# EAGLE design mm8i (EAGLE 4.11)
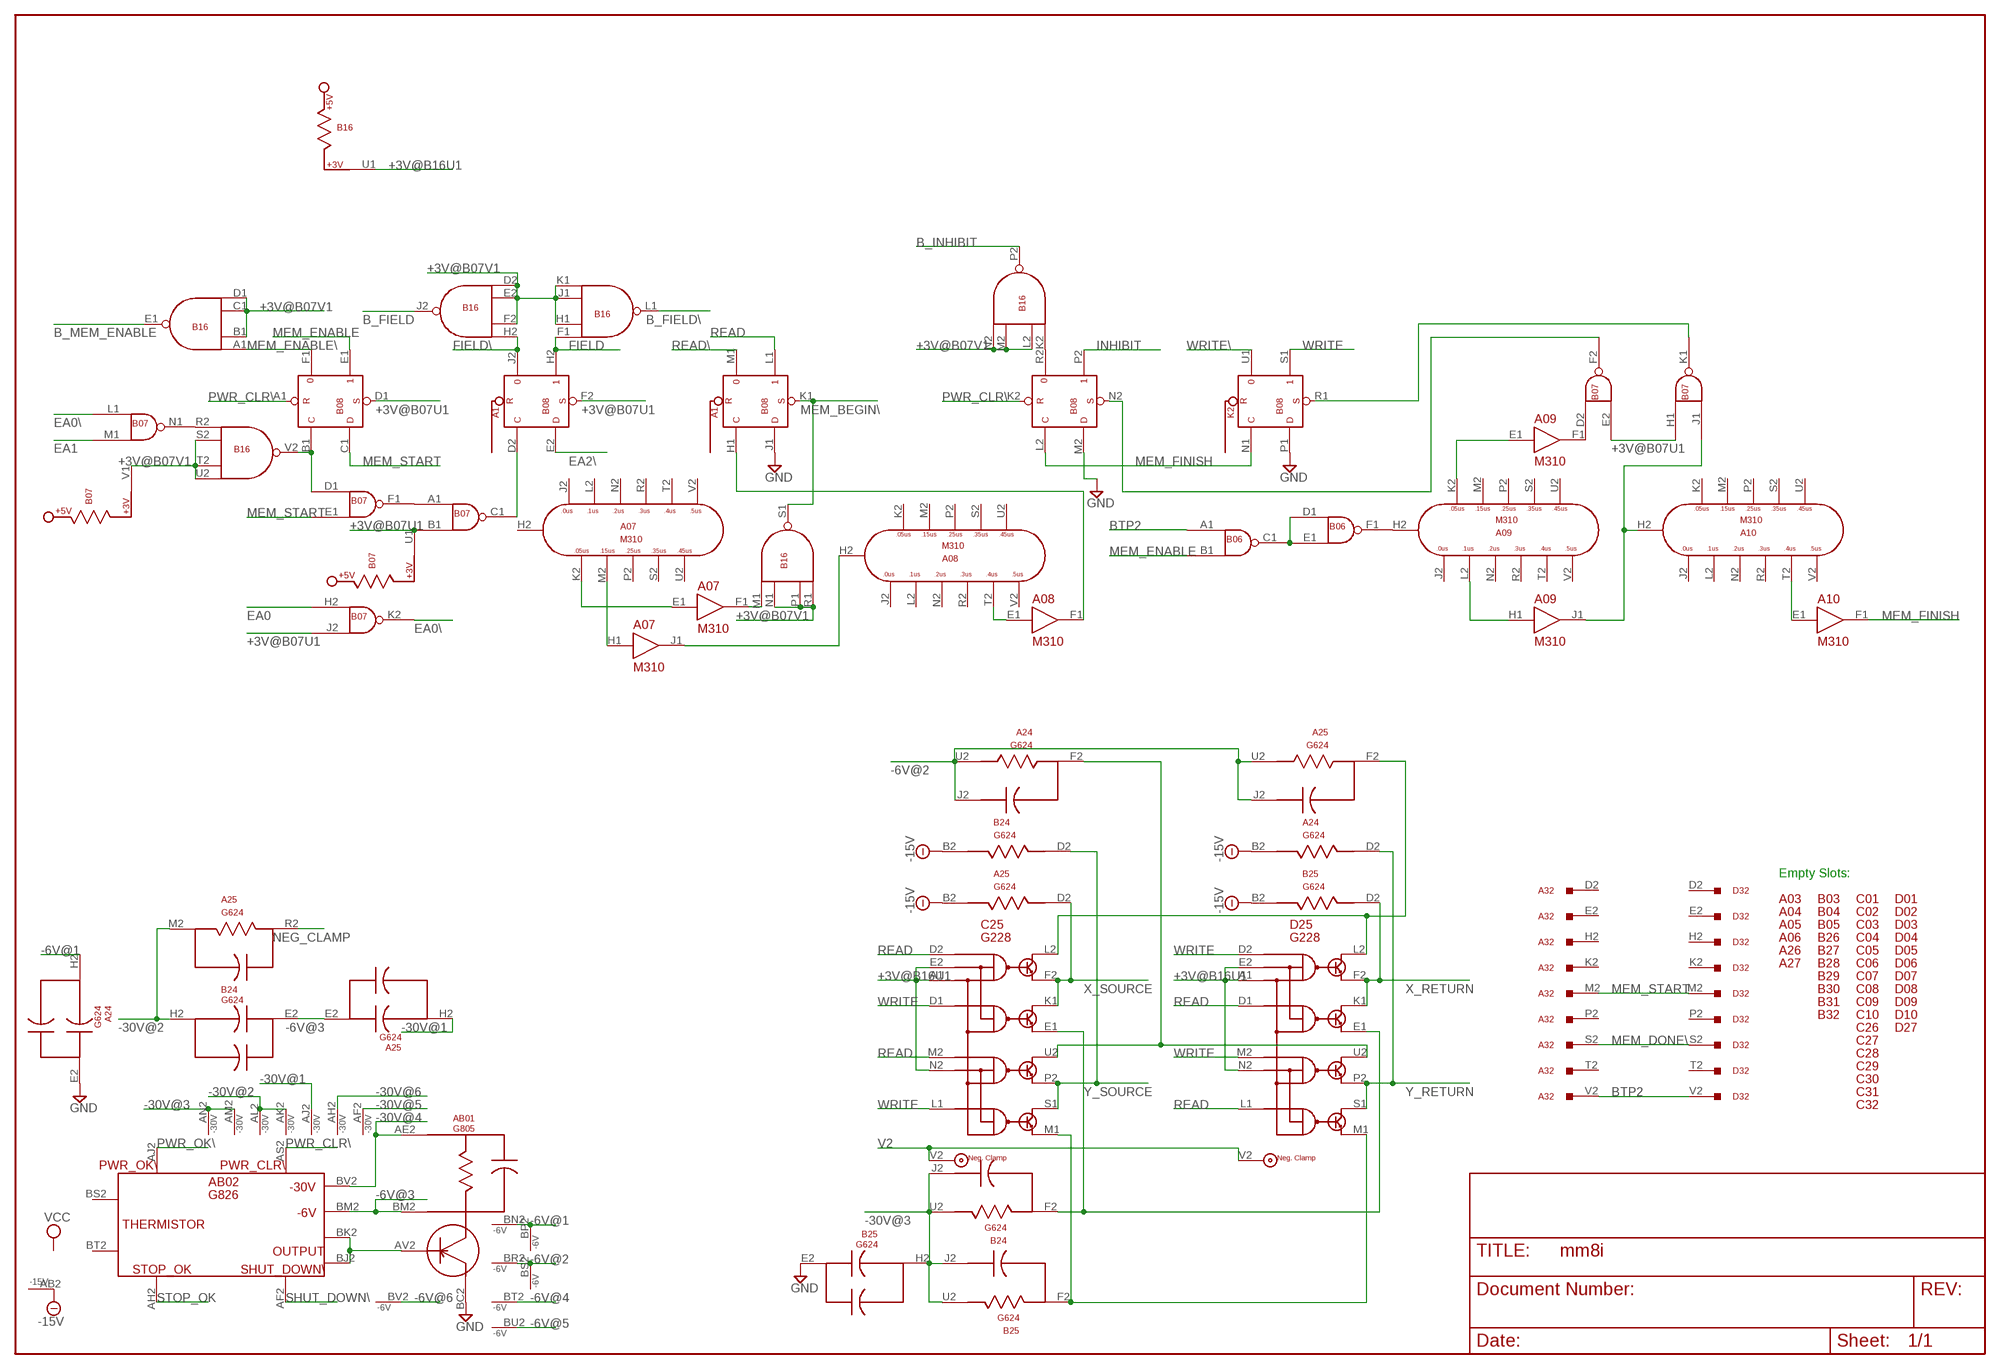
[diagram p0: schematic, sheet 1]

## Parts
A03  H807  [H807]
A04  H807  [H807]
A05  H807  [H807]
A06  H807  [H807]
A07  M310  [H807]
A08  M310  [H807]
A09  M310  [H807]
A10  M310  [H807]
A24  G624  [H807]
A25  G624  [H807]
A26  H807  [H807]
A27  H807  [H807]
A32  W033  W011  [H807]
AB01  G805  [H807-2]
AB02  G826  [H807-2]
B03  H807  [H807]
B04  H807  [H807]
B05  H807  [H807]
B06  M113  [H807]
B07  M113  [H807]
B08  M216  M206X  [H807]
B16  M617  [H807]
B24  G624  [H807]
B25  G624  [H807]
B26  H807  [H807]
B27  H807  [H807]
B28  H807  [H807]
B29  H807  [H807]
B30  H807  [H807]
B31  H807  [H807]
B32  H807  [H807]
C01  H807  [H807]
C02  H807  [H807]
C03  H807  [H807]
C04  H807  [H807]
C05  H807  [H807]
C06  H807  [H807]
C07  H807  [H807]
C08  H807  [H807]
C09  H807  [H807]
C10  H807  [H807]
C25  G228  [H807]
C26  H807  [H807]
C27  H807  [H807]
C28  H807  [H807]
C29  H807  [H807]
C30  H807  [H807]
C31  H807  [H807]
C32  H807  [H807]
D01  H807  [H807]
D02  H807  [H807]
D03  H807  [H807]
D04  H807  [H807]
D05  H807  [H807]
D06  H807  [H807]
D07  H807  [H807]
D08  H807  [H807]
D09  H807  [H807]
D10  H807  [H807]
D25  G228  [H807]
D27  H807  [H807]
D32  W033  W011  [H807]

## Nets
+3V@B07U1: B07.B1(IN2) B07.E2(IN2) B07.H1(IN1) B07.J2(IN2) B07.U1 B08.D1(A1:S) B08.F2(A1B:S)
+3V@B07V1: B07.V1 B16.B1(IN2) B16.C1(IN3) B16.D1(IN4) B16.D2(IN1) B16.E2(IN2) B16.F2(IN3) B16.H1(IN2) B16.J1(IN3) B16.K1(IN4) B16.L2(IN2) B16.M2(IN3) B16.N1(IN2) B16.N2(IN4) B16.P1(IN3) B16.R1(IN4) B16.S2(IN2) B16.T2(IN3) B16.U2(IN4)
+3V@B16U1: B16.U1 C25.A1 C25.E2 C25.N2 D25.A1 D25.E2 D25.N2
-6V@1: A24.H2 AB01.BN2(-6V) AB01.BP2(-6V)
-6V@2: A24.J2 A24.U2 A25.J2 A25.U2 AB01.BR2(-6V) AB01.BS2(-6V)
-6V@3 [supply]: A25.E2 AB01.BM2(-6V) AB02.BM2(-6V) B24.E2
-6V@4: AB01.BT2(-6V)
-6V@5: AB01.BU2(-6V)
-6V@6: AB01.BV2(-6V)
-15V: A24.B2 A25.B2 AB02.AB2(-15V) B24.B2 B25.B2
-30V@1: A25.H2 AB01.AJ2(-30V)
-30V@2: A25.M2 AB01.AK2(-30V) AB01.AL2(-30V) B24.H2
-30V@3: AB01.AM2(-30V) AB01.AN2(-30V) B24.J2 B24.U2 B25.H2 B25.J2 B25.U2
-30V@4 [supply]: AB01.AE2(-30V) AB02.BV2(-30V)
-30V@5: AB01.AF2(-30V)
-30V@6: AB01.AH2(-30V)
B_FIELD: B16.J2(OUT)
B_FIELD\: B16.L1(OUT)
B_INHIBIT: B16.P2(OUT)
B_MEM_ENABLE: B16.E1(OUT)
BTP2: A32.V2 B06.A1(IN1) D32.V2
EA0: B07.H2(IN1)
EA0\: B07.K2(OUT) B07.L1(IN1)
EA1: B07.M1(IN2)
EA2\: B08.E2(A1B:D)
FIELD: B08.H2 B16.F1(IN1)
FIELD\: B08.J2 B16.H2(IN4)
GND [supply]: A24.E2 AB01.BC2(GND) B08.J1(A1C:D) B08.M2(K2:D) B08.P1(K2B:D) B25.E2
INHIBIT: B08.P2
MEM_BEGIN\: B08.K1(A1C:S) B16.S1(OUT)
MEM_DONE\: A32.S2 D32.S2
MEM_ENABLE: B06.B1(IN2) B08.E1
MEM_ENABLE\: B08.F1 B16.A1(IN1)
MEM_FINISH: A10.F1(OUT) B08.L2(K2:C) B08.N1(K2B:C)
MEM_START: A32.M2 B07.E1(IN2) B08.C1(A1:D) D32.M2
N$1: AB01.AV2 AB02.BJ2 AB02.BK2
N$2: B06.C1(OUT) B06.D1(IN1) B06.E1(IN2)
N$3: A25.F2 C25.L2 D25.L2
N$4: A24.F2 C25.U2 D25.U2
N$5: B07.N1(OUT) B16.R2(IN1)
N$6: B07.D1(IN1) B08.B1(A1:C) B16.V2(OUT)
N$7: B07.A1(IN1) B07.F1(OUT)
N$8: B07.C1(OUT) B08.D2(A1B:C)
N$9: A07.H1(IN) A07.M2
N$10: A07.E1(IN) A07.K2
N$11: A07.F1(OUT) B16.M1(IN1)
N$12: A07.J1(OUT) A08.H2
N$13: A08.E1(IN) A08.T2
N$14: A08.F1(OUT) B08.H1(A1C:C)
N$15: A09.H2 B06.F1(OUT)
N$16: A09.E1(IN) A09.K2
N$17: A09.H1(IN) A09.L2
N$18: A09.F1(OUT) B07.D2(IN1)
N$19: B25.F2 C25.M1 D25.M1
N$20: B24.F2 C25.E1 D25.E1
N$21: B07.F2(OUT) B08.N2(K2:S)
N$22: B08.R2 B16.K2(IN1)
N$23: A09.J1(OUT) A10.H2 B07.J1(IN2)
N$24: A10.E1(IN) A10.T2
N$25: B07.K1(OUT) B08.R1(K2B:S)
NEG_CLAMP: A25.R2
PWR_CLR\: AB02.AS2 B08.A1(A1:R) B08.K2(K2:R)
PWR_OK\: AB02.AJ2
READ: B08.L1 C25.D2 C25.M2 D25.D1 D25.L1
READ\: B08.M1
SHUT_DOWN\: AB02.AF2
STOP_OK: AB02.AH2
V2: C25.V2 D25.V2
WRITE: B08.S1 C25.D1 C25.L1 D25.D2 D25.M2
WRITE\: B08.U1
X_RETURN: B25.D2 D25.F2 D25.K1
X_SOURCE: A25.D2 C25.F2 C25.K1
Y_RETURN: A24.D2 D25.P2 D25.S1
Y_SOURCE: B24.D2 C25.P2 C25.S1
Unconnected: A07.H2 A07.J2 A07.L2 A07.N2 A07.P2 A07.R2 A07.S2 A07.T2 A07.U2 A07.V2 A08.H1(IN) A08.J1(OUT) A08.J2 A08.K2 A08.L2 A08.M2 A08.N2 A08.P2 A08.R2 A08.S2 A08.U2 A08.V2 A09.J2 A09.M2 A09.N2 A09.P2 A09.R2 A09.S2 A09.T2 A09.U2 A09.V2 A10.H1(IN) A10.J1(OUT) A10.J2 A10.K2 A10.L2 A10.M2 A10.N2 A10.P2 A10.R2 A10.S2 A10.U2 A10.V2 A24.C2 A24.K2 A24.L2 A24.M2 A24.N2 A24.P2 A24.R2 A24.S2 A24.T2 A24.V2 A25.C2 A25.K2 A25.L2 A25.N2 A25.P2 A25.S2 A25.T2 A25.V2 A32.D2 A32.E2 A32.H2 A32.K2 A32.P2 A32.T2 AB02.BS2 AB02.BT2 B06.D2(IN1) B06.E2(IN2) B06.F2(OUT) B06.H1(IN1) B06.H2(IN1) B06.J1(IN2) B06.J2(IN2) B06.K1(OUT) B06.K2(OUT) B06.L1(IN1) B06.L2(IN1) B06.M1(IN2) B06.M2(IN2) B06.N1(OUT) B06.N2(OUT) B06.P1(IN1) B06.P2(IN1) B06.R1(IN2) B06.R2(IN2) B06.S1(OUT) B06.S2(OUT) B06.T2(IN1) B06.U1 B06.U2(IN2) B06.V1 B06.V2(OUT) B07.L2(IN1) B07.M2(IN2) B07.N2(OUT) B07.P1(IN1) B07.P2(IN1) B07.R1(IN2) B07.R2(IN2) B07.S1(OUT) B07.S2(OUT) B07.T2(IN1) B07.U2(IN2) B07.V2(OUT) B08.S2(K2C:C) B08.T2(K2C:D) B08.U2(K2C:S) B08.V1 B08.V2 B16.V1 B24.C2 B24.K2 B24.L2 B24.M2 B24.N2 B24.P2 B24.R2 B24.S2 B24.T2 B24.V2 B25.C2 B25.K2 B25.L2 B25.M2 B25.N2 B25.P2 B25.R2 B25.S2 B25.T2 B25.V2 D32.D2 D32.E2 D32.H2 D32.K2 D32.P2 D32.T2

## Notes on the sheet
- Empty Slots:

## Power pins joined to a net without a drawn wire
GND: A07.C2(GND) A07.T1(GND) A08.C2(GND) A08.T1(GND) A09.C2(GND) A09.T1(GND) A10.C2(GND) A10.T1(GND) A32.C2 A32.F2 A32.J2 A32.L2 A32.N2 A32.R2 A32.U2 AB01.BD2(GND) AB01.BE2(GND) AB01.BF2(GND) AB01.BH2(GND) AB01.BJ2(GND) AB01.BK2(GND) AB01.BL2(GND) AB02.AC2(GND) AB02.BC2(GND) B06.C2(GND) B06.T1(GND) B07.C2(GND) B07.T1(GND) B08.C2(GND) B08.T1(GND) B16.C2(GND) B16.T1(GND) C25.C2(GND) D25.C2(GND) D32.C2 D32.F2 D32.J2 D32.L2 D32.N2 D32.R2 D32.U2
VCC: A07.A2(VCC) A08.A2(VCC) A09.A2(VCC) A10.A2(VCC) AB02.AA2(VCC) AB02.BA2(VCC) B06.A2(VCC) B07.A2(VCC) B08.A2(VCC) B16.A2(VCC) C25.A2(VCC) D25.A2(VCC)

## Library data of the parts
A03-A06 A26 A27 B03-B05 B26-B32 C01-C09 C10 C26-C32 D01-D09 D10 D27 = dec-m:H807: Empty card slot
A07-A09 A10 = dec-m:M310: Tapped Delay Line
A24 A25 B24 B25 = dec-m:G624: Resistor Board
A32 D32 = dec-m:W011: One-sided 9 pin connector/cable with grounds (Negibus).
AB01 = dec-m:G805: Negative Regulator
AB02 = dec-m:G826: Regulator and Power Detector
B06 B07 = dec-m:M113: 10 2-input NAND Gates
B08 = dec-m:M206X: Two sets of 3 D flip-flops
B16 = dec-m:M617: 6 4-input NAND Buffers
C25 D25 = dec-m:G228: Inhibit Driver

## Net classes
1 supply: width 0.508 mm

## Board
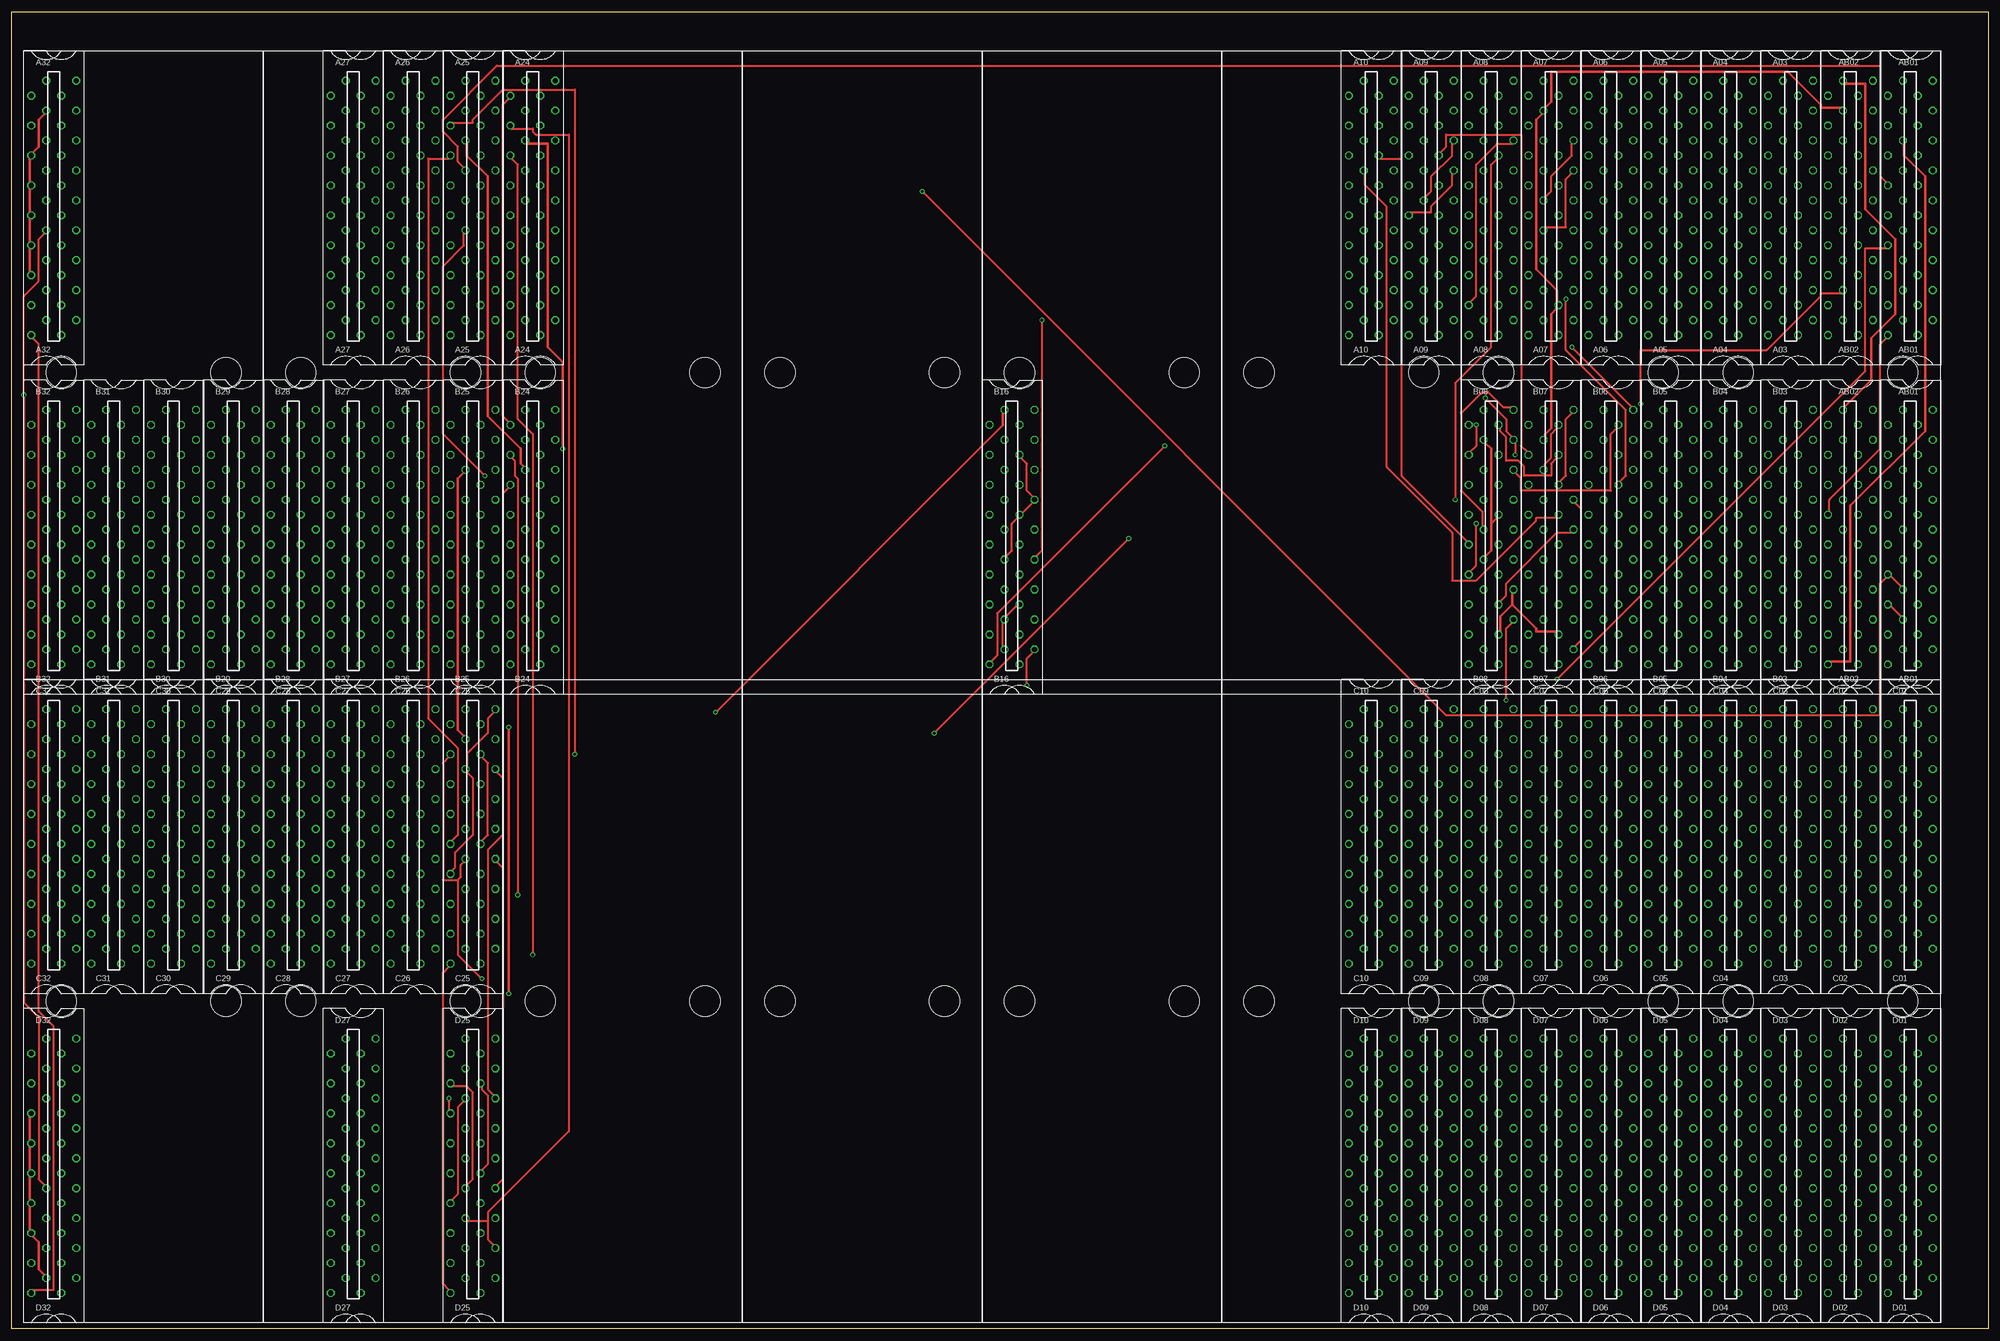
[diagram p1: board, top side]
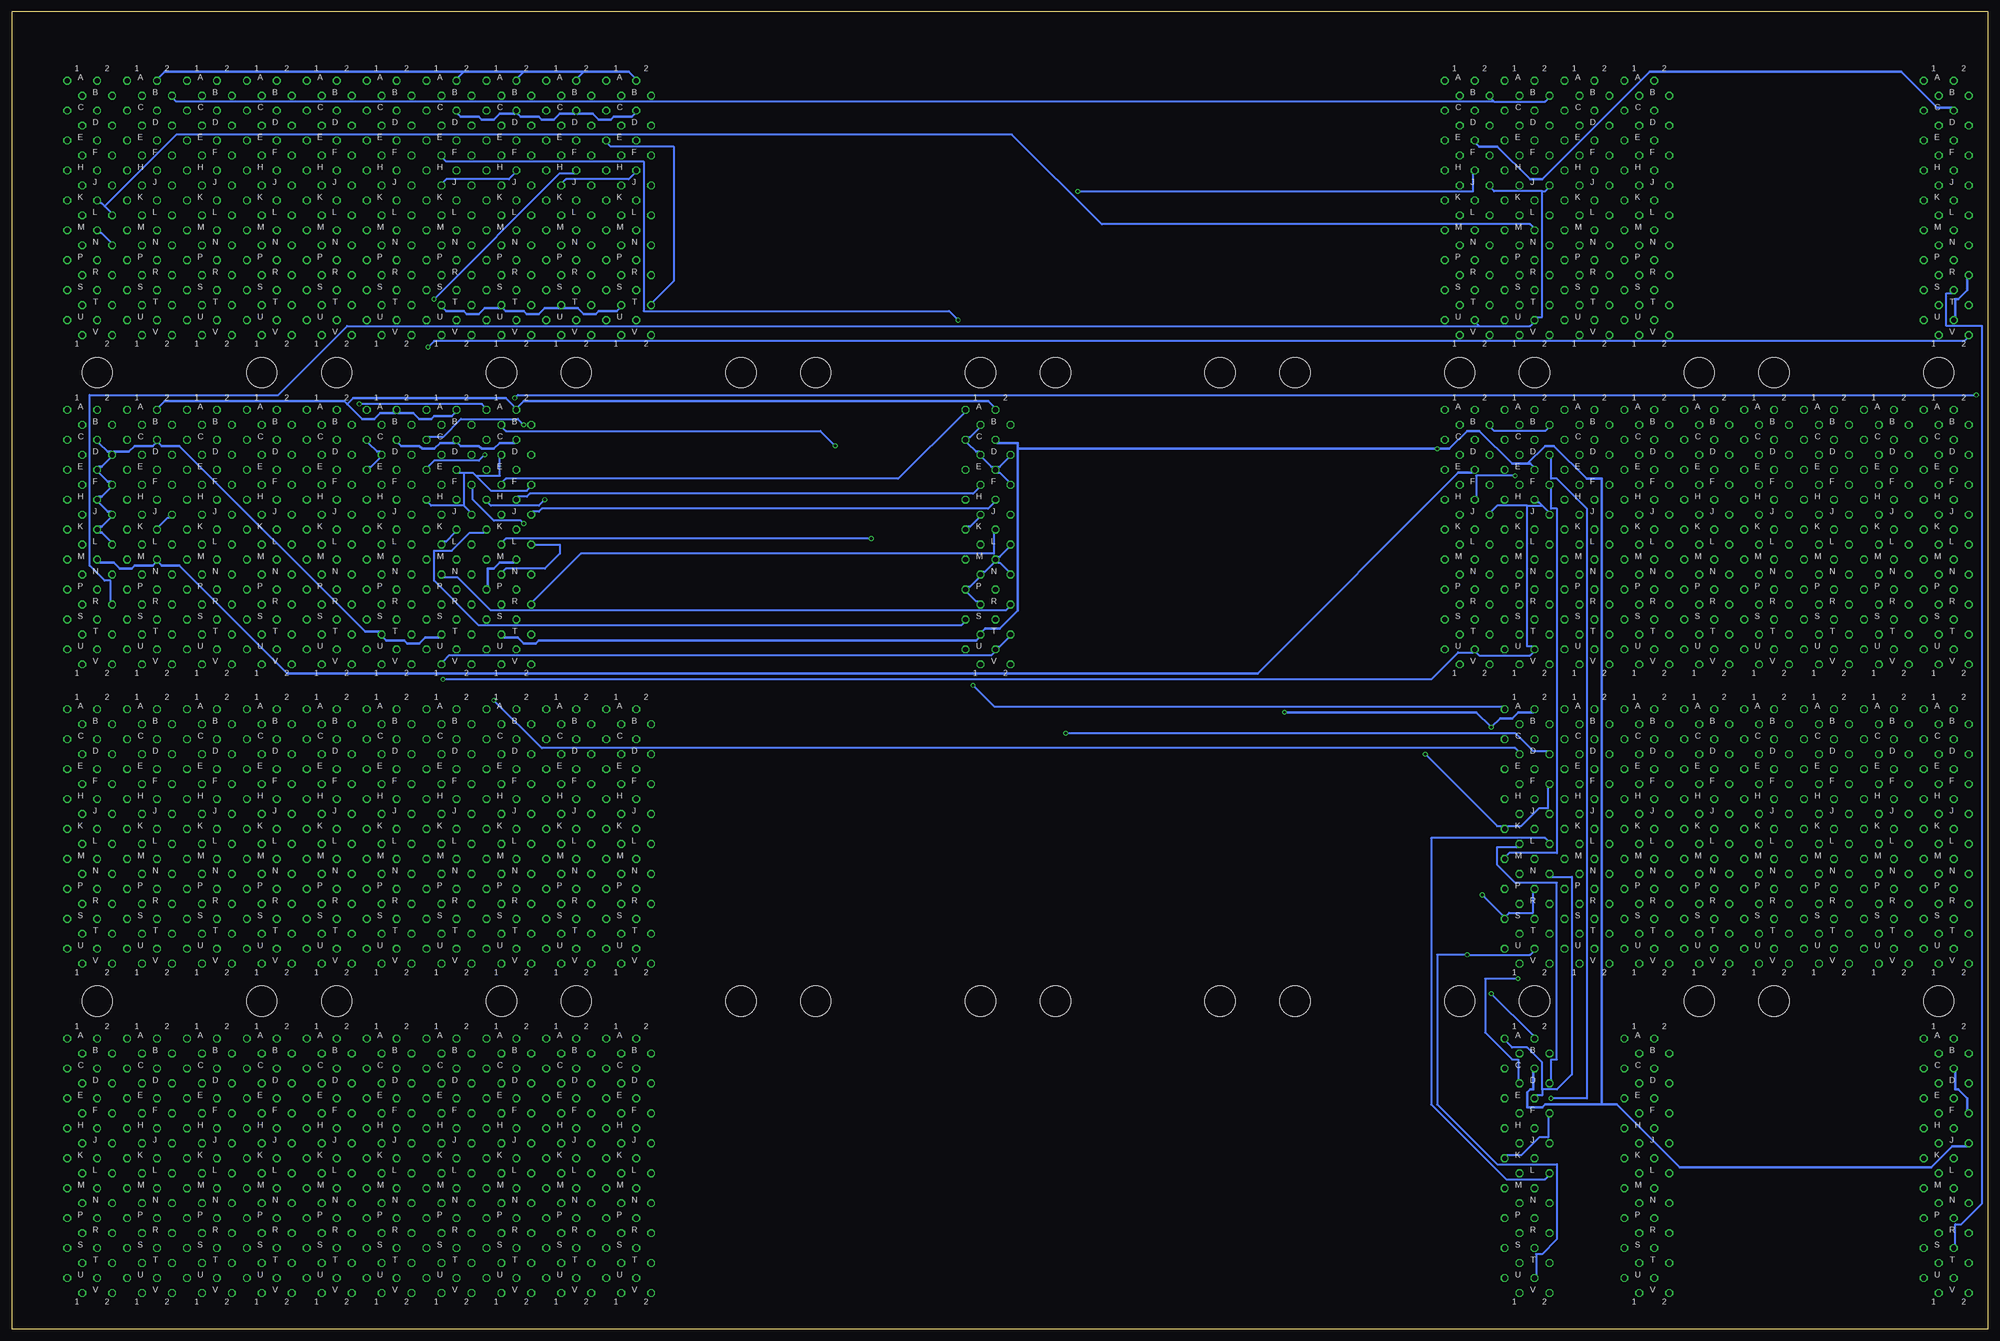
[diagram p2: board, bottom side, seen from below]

Size 419.1 x 279.4 mm. Coordinates in mm from the lower left corner, seen from the top.
Outline: 0,0 0,279.4 419.1,279.4 419.1,0 0,0
Copper layers (1*16): Top 0.035mm / dielectric 1.5mm / Bottom 0.035mm
Design rules "15mils": minimum track width 15mil, minimum drill 24mil, track to track 15mil, track to pad 10mil, pad to pad 10mil, via to via 10mil, smd to smd 10mil, copper to edge 25mil, drill to drill 10mil, minimum pad ring 10mil, minimum via ring 8mil, stop-mask expansion 0mil, vias tented up to drill 0mil, thermal gap 10mil

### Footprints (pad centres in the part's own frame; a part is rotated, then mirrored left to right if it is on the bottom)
H807 = drill 1.092 octagon: A1 4.763,28.575; A2 -1.587,28.575; B1 1.587,25.4; B2 -4.763,25.4; C1 4.763,22.225; C2 -1.587,22.225; D1 1.587,19.05; D2 -4.763,19.05; E1 4.763,15.875; E2 -1.587,15.875; F1 1.587,12.7; F2 -4.763,12.7; H1 4.763,9.525; H2 -1.587,9.525; J1 1.587,6.35; J2 -4.763,6.35; K1 4.763,3.175; K2 -1.587,3.175; L1 1.587,0; L2 -4.763,0; M1 4.763,-3.175; M2 -1.587,-3.175; N1 1.587,-6.35; N2 -4.763,-6.35; P1 4.763,-9.525; P2 -1.587,-9.525; R1 1.587,-12.7; R2 -4.763,-12.7; S1 4.763,-15.875; S2 -1.587,-15.875; T1 1.587,-19.05; T2 -4.763,-19.05; U1 4.763,-22.225; U2 -1.587,-22.225; V1 1.587,-25.4; V2 -4.763,-25.4
H807-2 = drill 1.092 octagon: AA1 4.763,60.325; AA2 -1.587,60.325; AB1 1.587,57.15; AB2 -4.763,57.15; AC1 4.763,53.975; AC2 -1.587,53.975; AD1 1.587,50.8; AD2 -4.763,50.8; AE1 4.763,47.625; AE2 -1.587,47.625; AF1 1.587,44.45; AF2 -4.763,44.45; AH1 4.763,41.275; AH2 -1.587,41.275; AJ1 1.587,38.1; AJ2 -4.763,38.1; AK1 4.763,34.925; AK2 -1.587,34.925; AL1 1.587,31.75; AL2 -4.763,31.75; AM1 4.763,28.575; AM2 -1.587,28.575; AN1 1.587,25.4; AN2 -4.763,25.4; AP1 4.763,22.225; AP2 -1.587,22.225; AR1 1.587,19.05; AR2 -4.763,19.05; AS1 4.763,15.875; AS2 -1.587,15.875; AT1 1.587,12.7; AT2 -4.763,12.7; AU1 4.763,9.525; AU2 -1.587,9.525; AV1 1.587,6.35; AV2 -4.763,6.35; BA1 4.763,-9.525; BA2 -1.587,-9.525; BB1 1.587,-12.7; BB2 -4.763,-12.7; BC1 4.763,-15.875; BC2 -1.587,-15.875; BD1 1.587,-19.05; BD2 -4.763,-19.05; BE1 4.763,-22.225; BE2 -1.587,-22.225; BF1 1.587,-25.4; BF2 -4.763,-25.4; BH1 4.763,-28.575; BH2 -1.587,-28.575; BJ1 1.587,-31.75; BJ2 -4.763,-31.75; BK1 4.763,-34.925; BK2 -1.587,-34.925; BL1 1.587,-38.1; BL2 -4.763,-38.1; BM1 4.763,-41.275; BM2 -1.587,-41.275; BN1 1.587,-44.45; BN2 -4.763,-44.45; BP1 4.763,-47.625; BP2 -1.587,-47.625; BR1 1.587,-50.8; BR2 -4.763,-50.8; BS1 4.763,-53.975; BS2 -1.587,-53.975; BT1 1.587,-57.15; BT2 -4.763,-57.15; BU1 4.763,-60.325; BU2 -1.587,-60.325; BV1 1.587,-63.5; BV2 -4.763,-63.5
CBLOCK = hole 6.452: 7.938,68.263; 42.862,68.263

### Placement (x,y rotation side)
A03  377.19,236.22 0 top
A04  364.49,236.22 0 top
A05  351.79,236.22 0 top
A06  339.09,236.22 0 top
A07  326.39,236.22 0 top
A08  313.69,236.22 0 top
A09  300.99,236.22 0 top
A10  288.29,236.22 0 top
A24  110.49,236.22 0 top
A25  97.79,236.22 0 top
A26  85.09,236.22 0 top
A27  72.39,236.22 0 top
A32  8.89,236.22 0 top
AB01  402.59,204.47 0 top
AB02  389.89,204.47 0 top
B03  377.19,166.37 0 top
B04  364.49,166.37 0 top
B05  351.79,166.37 0 top
B06  339.09,166.37 0 top
B07  326.39,166.37 0 top
B08  313.69,166.37 0 top
B16  212.09,166.37 0 top
B24  110.49,166.37 0 top
B25  97.79,166.37 0 top
B26  85.09,166.37 0 top
B27  72.39,166.37 0 top
B28  59.69,166.37 0 top
B29  46.99,166.37 0 top
B30  34.29,166.37 0 top
B31  21.59,166.37 0 top
B32  8.89,166.37 0 top
C01  402.59,102.87 0 top
C02  389.89,102.87 0 top
C03  377.19,102.87 0 top
C04  364.49,102.87 0 top
C05  351.79,102.87 0 top
C06  339.09,102.87 0 top
C07  326.39,102.87 0 top
C08  313.69,102.87 0 top
C09  300.99,102.87 0 top
C10  288.29,102.87 0 top
C25  97.79,102.87 0 top
C26  85.09,102.87 0 top
C27  72.39,102.87 0 top
C28  59.69,102.87 0 top
C29  46.99,102.87 0 top
C30  34.29,102.87 0 top
C31  21.59,102.87 0 top
C32  8.89,102.87 0 top
D01  402.59,33.02 0 top
D02  389.89,33.02 0 top
D03  377.19,33.02 0 top
D04  364.49,33.02 0 top
D05  351.79,33.02 0 top
D06  339.09,33.02 0 top
D07  326.39,33.02 0 top
D08  313.69,33.02 0 top
D09  300.99,33.02 0 top
D10  288.29,33.02 0 top
D25  97.79,33.02 0 top
D27  72.39,33.02 0 top
D32  8.89,33.02 0 top
U$1  [CBLOCK]  2.54,1.27 0 top
U$2  [CBLOCK]  53.34,1.27 0 top
U$3  [CBLOCK]  104.14,1.27 0 top
U$4  [CBLOCK]  154.94,1.27 0 top
U$5  [CBLOCK]  205.74,1.27 0 top
U$6  [CBLOCK]  256.54,1.27 0 top
U$7  [CBLOCK]  307.34,1.27 0 top
U$8  [CBLOCK]  358.14,1.27 0 top
U$9  [CBLOCK]  2.54,134.62 0 top
U$10  [CBLOCK]  53.34,134.62 0 top
U$11  [CBLOCK]  104.14,134.62 0 top
U$12  [CBLOCK]  154.94,134.62 0 top
U$13  [CBLOCK]  205.74,134.62 0 top
U$14  [CBLOCK]  256.54,134.62 0 top
U$15  [CBLOCK]  358.14,134.62 0 top
U$16  [CBLOCK]  307.34,134.62 0 top

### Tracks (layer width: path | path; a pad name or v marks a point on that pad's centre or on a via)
+3V@B07U1
  Top 0.381: B07.B1 327.66,191.13 326.39,189.87 326.39,184.78 325.12,183.51 325.12,182.88 B07.E2 | B07.U1 331.47,144.78 332.74,146.05 332.74,173.99 331.47,175.26 B07.H1
  Bottom 0.381: 320.68,180.97 321.31,181.61 323.21,181.61 | 320.68,180.97 317.5,177.8 309.88,177.8 309.25,178.44 B08.F2 | 323.21,181.61 324.49,181.61 B07.E2 | 320.68,180.97 315.6,180.97 315.6,184.78 B08.D1 | 323.21,174.62 321.94,173.35 B07.J2 | 323.21,174.62 330.2,174.62 330.83,175.26 B07.H1 | 323.21,181.61 323.21,174.62
+3V@B07V1
  Top 0.381: B16.D1 214,184.78 215.26,183.51 215.26,177.8 216.53,176.53 B16.H1 216.53,175.26 214,172.72 B16.J1 213.36,172.09 212.09,170.81 212.09,165.1 210.82,163.83 B16.M2 | B16.R1 213.36,153.67 210.82,151.13 B16.S2 210.19,149.86 210.19,144.78 B16.U2
  Bottom 0.381: B16.J1 214,172.09 215.9,170.18 216.53,170.18 B16.K1 | B16.F2 207.65,179.71 209.55,181.61 210.19,181.61 B16.E2 | B16.D2 207.65,184.78 209.55,182.88 210.19,182.88 B16.E2 | B16.E2 210.82,182.88 211.46,182.88 213.36,184.78 B16.D1 214,186.06 214.63,186.06 216.53,187.96 B16.C1 216.53,189.23 215.9,189.23 214,191.13 B16.B1 | B16.N2 207.65,160.66 209.55,162.56 210.19,162.56 B16.M2 | B16.L2 207.65,165.74 209.55,163.83 210.19,163.83 B16.M2 | B16.R1 214,154.31 214.63,154.31 216.53,156.21 B16.P1 216.53,157.48 215.9,157.48 214,159.38 B16.N1 213.36,160.66 212.72,160.66 210.82,162.56 B16.M2 | B16.T2 207.65,146.69 209.55,144.78 210.19,144.78 B16.U2 210.82,143.51 211.46,142.88 326.39,142.88 327.66,141.6 B07.V1
+3V@B16U1  (via drill 0.61)
  Top 0.381: D25.N2 93.34,27.3 94.61,28.57 94.61,46.99 95.89,48.26 D25.E2 | C25.N2 93.34,97.16 93.98,97.79 93.98,100.97 97.79,104.78 97.79,116.84 96.52,118.11 C25.E2 96.52,119.38 96.52,121.92 100.97,126.36 100.97,129.54 102.23,130.81 C25.A1 | v215.26,136.53 215.26,142.24 216.53,143.51 B16.U1
  Bottom 0.381: 94.61,50.8 94.61,49.53 95.89,49.53 D25.E2 | 94.61,50.8 94.61,56.52 97.79,59.69 100.97,59.69 102.23,60.96 D25.A1 | v215.26,136.53 210.82,132.08 102.87,132.08 C25.A1 | 94.61,50.8 91.44,50.8 88.27,53.98 88.27,95.89 92.71,95.89 C25.N2
-6V@1  (via drill 0.61)
  Top 0.381: AB01.BP2 400.69,157.48 398.14,160.02 AB01.BN2 397.51,159.38 396.24,158.12 396.24,130.18 304.17,130.18 v193.04,241.3
  Bottom 0.381: v193.04,241.3 109.22,241.3 109.22,245.11 A24.H2
-6V@2
  Top 0.381: AB01.BS2 400.69,151.13 398.14,153.67 AB01.BR2
  Bottom 0.381: 94.61,241.3 104.78,241.3 105.41,241.94 A24.J2 | 94.61,241.3 93.98,241.3 93.34,241.94 A25.J2 | 107.95,212.72 97.16,212.72 96.52,213.36 A25.U2 95.89,214.63 94.61,214.63 94.61,241.3 | 107.95,212.72 108.58,213.36 A24.U2 | 107.95,212.72 347.98,212.72 362.58,198.12 402.59,198.12 402.59,161.93 399.42,158.75 398.14,158.75 398.14,154.31 AB01.BR2
-6V@3
  Top 0.508: B24.E2 108.58,182.88 107.95,183.51 107.95,186.69 100.97,193.68 100.97,244.47 96.52,248.92 96.52,251.46 A25.E2
  Bottom 0.508: AB01.BM2 400.69,162.56 397.51,162.56 396.24,161.29 393.7,161.29 393.06,161.93 389.25,161.93 388.62,162.56 AB02.BM2 387.99,162.56 387.35,161.93 383.54,161.93 360.68,139.06 154.94,139.06 112.39,181.61 109.22,181.61 B24.E2
-15V
  Top 0.381: B24.B2 105.41,192.41 104.14,193.68 104.14,259.71 105.41,260.99 A24.B2
  Bottom 0.381: B25.B2 93.34,191.13 93.98,190.5 104.78,190.5 105.41,191.13 B24.B2 | 104.78,260.35 93.98,260.35 93.34,260.99 A25.B2 | 104.78,260.35 105.41,260.99 A24.B2 | 104.78,260.35 384.18,260.35 384.81,260.99 AB02.AB2
-30V@1
  Top 0.381: A25.H2 95.89,246.38 94.61,247.65 94.61,250.82 91.44,254 91.44,256.54 102.87,267.97 396.24,267.97 396.24,244.47 397.51,243.21 AB01.AJ2
-30V@2  (via drill 0.61)
  Top 0.381: v100.33,180.97 91.44,189.87 91.44,225.43 95.89,229.87 95.89,232.41 A25.M2
  Bottom 0.381: 399.42,238.12 400.05,238.76 400.69,238.76 AB01.AK2 | 399.42,238.12 398.14,236.85 AB01.AL2 | v100.33,180.97 108.58,180.97 108.58,176.53 B24.H2 | 399.42,238.12 384.18,253.37 207.01,253.37 187.96,234.31 97.16,234.31 96.52,233.68 A25.M2
-30V@3  (via drill 0.61)
  Top 0.381: v327.66,137.79 393.06,203.2 393.06,229.24 397.51,229.24 AB01.AN2
  Bottom 0.381: 94.61,174.62 95.25,175.26 95.89,175.26 B25.H2 | 94.61,174.62 93.34,173.35 B25.J2 | 97.79,174.62 94.61,174.62 | 97.79,174.62 104.14,174.62 105.41,173.35 B24.J2 | AB01.AN2 398.14,230.5 400.05,232.41 400.69,232.41 AB01.AM2 | v327.66,137.79 118.11,137.79 112.39,143.51 109.22,143.51 B24.U2 108.58,143.51 107.95,142.88 97.16,142.88 96.52,143.51 B25.U2 96.52,144.78 97.79,144.78 97.79,174.62
-30V@4
  Top 0.508: AB02.BV2 385.44,141.6 389.89,141.6 389.89,174.62 405.76,190.5 405.76,244.47 401.32,248.92 401.32,251.46 AB01.AE2
BTP2  (via drill 0.61)
  Top 0.381: D32.V2 4.45,8.26 8.89,8.26 8.89,64.14 5.71,67.31 5.71,208.91 4.45,210.19 A32.V2 | v330.83,208.28 343.54,195.58 B06.A1
  Bottom 0.381: v330.83,208.28 329.56,209.55 5.08,209.55 4.45,210.19 A32.V2
EA0\
  Bottom 0.381: B07.K2 325.12,168.91 327.02,167 327.66,167 B07.L1
FIELD
  Bottom 0.381: B16.F1 214,178.44 215.26,177.16 309.25,177.16 309.88,176.53 311.79,176.53 B08.H2
FIELD\
  Bottom 0.381: B16.H2 210.82,175.26 212.09,173.99 306.7,173.99 307.34,173.35 308.61,173.35 B08.J2
GND  (via drill 0.61)
  Top 0.508: A32.R2 3.81,224.16 3.81,229.24 A32.N2 3.81,230.5 3.81,235.59 A32.L2 3.81,236.85 3.81,241.94 A32.J2 3.81,243.21 3.81,248.28 A32.F2 4.45,249.56 5.71,250.82 5.71,256.54 6.99,257.81 A32.C2 | D32.F2 3.81,45.09 3.81,40.01 D32.J2 3.81,38.73 3.81,33.66 D32.L2 3.81,32.38 3.81,27.3 D32.N2 3.81,26.04 3.81,20.95 D32.R2 4.45,19.68 5.71,18.41 5.71,12.7 6.99,11.43 D32.U2 | AB02.AC2 387.99,259.08 383.54,259.08 383.54,259.71 376.56,266.7 326.39,266.7 326.39,260.35 325.12,259.08 A07.C2 324.49,257.81 323.21,256.54 323.21,224.79 327.66,220.34 327.66,217.81 A07.T1 327.66,216.53 326.39,215.26 326.39,191.13 325.12,189.87 325.12,189.23 B07.C2 | C25.C2 95.89,125.73 94.61,127 94.61,180.34 95.89,181.61 B25.E2 | 318.13,153.67 315.6,151.13 315.6,147.96 B08.T1 | 318.13,153.67 318.13,156.21 B08.P1 | 318.13,153.67 323.21,148.59 323.21,147.96 327.66,147.96 B07.T1 | 313.69,170.81 313.69,165.1 312.42,163.83 B08.M2 | 313.69,170.81 314.96,172.09 B08.J1 | 313.69,170.81 313.69,186.69 312.42,187.96 B08.C2 | v116.84,186.69 116.84,205.1 113.67,208.28 113.67,251.46 109.22,251.46 A24.E2
  Bottom 0.508: A32.U2 6.99,214.63 6.99,218.44 6.35,218.44 4.45,220.34 4.45,222.88 A32.R2 | A24.E2 108.58,251.46 107.95,250.82 104.14,250.82 97.16,243.84 94.61,243.84 71.75,266.7 18.41,266.7 10.79,259.08 7.62,259.08 A32.C2 | D32.C2 6.99,54.61 6.99,50.8 6.35,50.8 4.45,48.9 4.45,46.35 D32.F2 | 81.92,47.62 78.74,47.62 65.41,34.29 12.06,34.29 7.62,38.73 4.45,38.73 D32.J2 | 81.92,47.62 93.98,47.62 94.61,46.99 97.79,46.99 97.79,50.16 97.16,50.8 96.52,50.8 96.52,54.61 D25.C2 | A10.C2 287.02,257.81 287.65,257.18 291.46,257.18 292.1,256.54 294.64,256.54 295.91,257.81 299.08,257.81 A09.C2 299.72,257.81 302.89,257.81 304.17,256.54 306.7,256.54 307.34,257.18 311.15,257.18 311.79,257.81 A08.C2 312.42,257.81 315.6,257.81 316.87,256.54 319.4,256.54 320.04,257.18 323.85,257.18 324.49,257.81 A07.C2 | 205.74,186.69 205.74,187.96 210.19,187.96 B16.C2 | 205.74,186.69 205.74,152.4 209.55,148.59 212.72,148.59 213.36,147.96 B16.T1 214,146.69 214.63,146.05 307.34,146.05 307.98,145.41 310.51,145.41 311.79,146.69 314.96,146.69 B08.T1 | A10.T1 290.19,216.53 290.83,215.9 294.64,215.9 295.27,215.26 297.81,215.26 299.08,216.53 302.26,216.53 A09.T1 302.89,216.53 306.07,216.53 307.34,215.26 309.88,215.26 310.51,215.9 314.32,215.9 314.96,216.53 A08.T1 315.6,216.53 318.77,216.53 320.04,215.26 322.58,215.26 323.21,215.9 327.02,215.9 327.66,216.53 A07.T1 | AB01.BL2 398.14,167 400.05,168.91 400.69,168.91 AB01.BK2 400.69,170.18 400.05,170.18 398.14,172.09 AB01.BJ2 398.14,173.35 398.78,173.35 400.69,175.26 AB01.BH2 400.69,176.53 400.05,176.53 398.14,178.44 AB01.BF2 398.14,179.71 398.78,179.71 400.69,181.61 AB01.BE2 400.69,182.88 400.05,182.88 398.14,184.78 AB01.BD2
  Bottom 0.508: AB01.BD2 397.51,186.06 394.33,186.06 393.06,187.32 389.25,187.32 388.62,187.96 AB02.BC2 387.99,187.96 387.35,187.32 383.54,187.32 344.17,147.96 341,147.96 B06.T1 340.36,146.69 339.73,146.05 335.92,146.05 335.28,145.41 332.74,145.41 331.47,146.69 328.3,146.69 B07.T1 | AB01.BC2 400.69,187.96 398.78,186.06 398.14,186.06 AB01.BD2 | B08.C2 312.42,187.96 315.6,187.96 316.87,186.69 319.4,186.69 320.04,187.32 323.85,187.32 324.49,187.96 B07.C2 325.12,187.96 328.3,187.96 329.56,186.69 332.11,186.69 332.74,187.32 336.55,187.32 337.19,187.96 B06.C2 | B08.P1 318.13,157.48 318.13,161.29 316.87,161.29 315.6,162.56 312.42,162.56 B08.M2 | 97.79,183.51 100.97,183.51 107.95,190.5 110.49,190.5 114.3,186.69 v116.84,186.69 205.74,186.69 | 97.79,183.51 97.16,183.51 96.52,182.88 B25.E2 | 81.92,47.62 81.92,180.34 85.09,180.34 92.08,187.32 93.98,187.32 97.79,183.51
MEM_BEGIN\
  Bottom 0.381: B16.S1 217.17,149.86 217.81,149.22 320.04,149.22 329.56,158.75 329.56,165.1 325.75,165.1 321.94,168.91 318.77,168.91 B08.K1
MEM_DONE\
  Bottom 0.381: D32.S2 6.99,17.78 6.99,22.23 5.71,22.23 1.27,26.67 1.27,212.72 8.89,212.72 8.89,219.71 7.62,219.71 A32.S2
MEM_ENABLE
  Top 0.381: B08.E1 318.77,181.61 320.04,180.34 320.04,177.8 339.09,177.8 339.09,189.87 340.36,191.13 B06.B1
MEM_ENABLE\
  Bottom 0.381: B16.A1 217.17,194.31 231.14,180.34 314.32,180.34 314.96,179.71 B08.F1
MEM_FINISH
  Top 0.381: A10.F1 290.19,248.28 294.64,248.28 294.64,180.97 308.61,167 B08.L2
  Bottom 0.381: B08.N1 314.96,160.66 314.32,161.29 306.07,161.29 302.89,164.47 302.89,166.37 B08.L2
MEM_START  (via drill 0.61)
  Top 0.381: v318.77,185.42 318.77,187.96 B08.C1 318.13,189.23 316.87,190.5 316.87,193.04 v312.42,197.49 | D32.M2 6.99,30.48 5.71,31.75 5.71,66.04 2.54,69.22 v2.54,198.12 2.54,219.07 5.71,222.25 5.71,231.14 6.99,232.41 A32.M2
  Bottom 0.381: v318.77,185.42 320.04,184.15 329.56,184.15 330.83,182.88 B07.E1 | v312.42,197.49 311.79,198.12 v2.54,198.12
N$1
  Top 0.381: AB01.AV2 397.51,210.19 396.24,208.91 396.24,186.69 385.44,175.9 385.44,173.35 AB02.BJ2
  Bottom 0.381: AB02.BK2 387.99,170.18 386.08,172.09 385.44,172.09 AB02.BJ2
N$2
  Bottom 0.381: B06.E1 343.54,182.88 342.9,182.88 341,184.78 B06.D1 341,186.06 341.63,186.06 343.54,187.96 B06.C1
N$3
  Top 0.381: A25.F2 92.71,248.28 88.27,248.28 88.27,129.54 94.61,123.19 94.61,104.78 93.34,103.5 C25.L2
  Bottom 0.381: D25.L2 93.34,32.38 93.98,31.75 102.23,31.75 118.11,47.62 118.11,104.14 93.98,104.14 93.34,103.5 C25.L2
N$4  (via drill 0.61)
  Top 0.381: v110.49,79.38 110.49,189.87 107.31,193.04 107.31,247.01 106.05,248.28 A24.F2
  Bottom 0.381: D25.U2 95.89,11.43 95.89,15.88 94.61,15.88 91.44,19.05 91.44,34.92 104.14,34.92 116.84,47.62 116.84,79.38 v110.49,79.38 97.16,79.38 96.52,80.01 C25.U2
N$5
  Bottom 0.381: B16.R2 207.65,153.03 208.28,152.4 317.5,152.4 324.49,159.38 327.66,159.38 B07.N1
N$6  (via drill 0.61)
  Top 0.381: v244.47,187.32 208.91,151.76 208.91,142.88 207.65,141.6 B16.V2 | B07.D1 327.66,184.78 326.39,183.51 326.39,180.97 320.68,180.97 320.68,182.88 319.4,184.15 316.87,184.15 316.87,189.23 315.6,190.5 315.6,191.13 B08.B1
  Bottom 0.381: v244.47,187.32 247.65,190.5 314.32,190.5 314.96,191.13 B08.B1
N$7
  Top 0.381: B07.F1 328.3,179.71 329.56,180.97 329.56,193.04 330.83,194.31 B07.A1
N$8  (via drill 0.61)
  Top 0.381: v310.51,191.77 310.51,187.32 309.25,186.06 B08.D2
  Bottom 0.381: v310.51,191.77 311.79,193.04 323.85,193.04 327.66,189.23 330.83,189.23 B07.C1
N$9
  Top 0.381: A07.M2 325.12,233.68 329.56,233.68 329.56,243.84 330.83,245.11 A07.H1
N$10
  Top 0.381: A07.K2 325.12,240.03 326.39,241.3 326.39,244.47 330.83,248.92 330.83,251.46 A07.E1
N$11  (via drill 0.61)
  Top 0.381: v218.44,214 218.44,165.1 217.17,163.83 B16.M1
  Bottom 0.381: v218.44,214 220.34,215.9 285.12,215.9 285.12,247.65 327.02,247.65 327.66,248.28 A07.F1
N$12
  Bottom 0.381: A08.H2 312.42,245.11 313.69,243.84 327.02,243.84 327.66,243.21 A07.J1
N$13
  Top 0.381: A08.T2 309.25,217.81 310.51,219.07 310.51,247.01 314.96,251.46 318.13,251.46 A08.E1
N$14  (via drill 0.61)
  Top 0.381: v306.07,175.9 306.07,200.66 313.69,208.28 313.69,247.01 314.96,248.28 A08.F1
  Bottom 0.381: v306.07,175.9 307.34,174.62 317.5,174.62 318.13,175.26 B08.H1
N$15  (via drill 0.61)
  Top 0.381: v329.56,218.44 329.56,207.65 342.26,194.94 342.26,180.97 341,179.71 B06.F1
  Bottom 0.381: v329.56,218.44 302.89,245.11 299.72,245.11 A09.H2
N$16
  Top 0.381: A09.K2 299.72,240.03 300.99,241.3 300.99,244.47 305.44,248.92 305.44,251.46 A09.E1
N$17
  Top 0.381: A09.L2 296.55,236.85 300.99,236.85 300.99,238.12 305.44,242.57 305.44,245.11 A09.H1
N$18
  Top 0.381: A09.F1 302.89,249.56 304.17,250.82 304.17,253.37 320.04,253.37 320.04,187.32 321.31,186.06 B07.D2
N$19
  Top 0.381: D25.M1 102.87,30.48 104.14,31.75 104.14,97.79 102.87,99.06 C25.M1
  Bottom 0.381: B25.F2 92.71,178.44 92.71,173.99 91.44,173.99 91.44,100.97 101.6,100.97 102.23,100.33 C25.M1
N$20
  Top 0.381: 104.14,116.84 104.14,104.78 100.97,101.6 100.97,50.8 102.23,49.53 D25.E1 | 104.14,116.84 102.87,118.11 C25.E1 | 104.14,116.84 104.14,177.16 105.41,178.44 B24.F2
N$21  (via drill 0.61)
  Top 0.381: v310.51,170.81 310.51,161.93 309.25,160.66 B08.N2
  Bottom 0.381: v310.51,170.81 311.15,171.45 316.87,171.45 321.31,175.9 321.31,178.44 B07.F2
N$22
  Bottom 0.381: B16.K2 210.82,168.91 210.82,164.47 298.45,164.47 308.61,154.31 B08.R2
N$23
  Top 0.381: B07.J1 327.66,172.09 323.21,172.09 323.21,171.45 310.51,158.75 305.44,158.75 305.44,168.91 291.46,182.88 291.46,238.12 287.02,242.57 287.02,245.11 A10.H2
  Bottom 0.381: A10.H2 287.02,245.11 288.29,243.84 301.62,243.84 302.26,243.21 A09.J1
N$24
  Bottom 0.381: A10.T2 283.21,217.81 278.76,222.25 278.76,250.82 292.1,250.82 292.74,251.46 A10.E1
N$25
  Top 0.381: B08.R1 315.6,154.31 316.87,155.57 316.87,158.12 327.66,168.91 330.83,168.91 B07.K1
PWR_CLR\  (via drill 0.61)
  Top 0.381: B08.K2 311.79,170.18 311.79,173.35 307.34,177.8 307.34,194.31 311.79,198.75 313.06,198.75 316.23,195.58 318.13,195.58 B08.A1 | v345.44,196.22 345.44,207.65 372.11,207.65 383.54,219.07 383.54,219.71 387.99,219.71 AB02.AS2
  Bottom 0.381: v345.44,196.22 319.4,196.22 318.77,195.58 B08.A1
READ  (via drill 0.61)
  Top 0.381: D25.L1 99.69,33.66 100.97,34.92 100.97,49.53 99.69,50.8 99.69,51.44 D25.D1 | 94.61,95.25 95.25,95.89 95.25,98.42 95.89,99.06 C25.M2 | 94.61,95.25 91.44,95.25 91.44,120.02 92.71,121.28 C25.D2 | v195.58,126.36 v236.85,167.64 | v99.69,74.3 94.61,79.38 94.61,95.25
  Bottom 0.381: v236.85,167.64 314.32,167.64 314.96,167 B08.L1 | v195.58,126.36 100.33,126.36 96.52,122.56 93.34,122.56 C25.D2 | v99.69,74.3 106.68,74.3 106.68,62.87 100.97,57.15 99.69,57.15 99.69,52.7 D25.D1
V2
  Top 0.381: D25.V2 92.71,8.26 91.44,9.53 91.44,75.56 92.71,76.83 C25.V2
VCC  (via drill 0.61)
  Top 0.508: v105.41,127.64 v105.41,71.12 | v149.22,130.81 210.19,191.77 210.19,194.31 B16.A2 | AB02.AA2 388.62,264.16 393.06,264.16 393.06,237.49 399.42,231.14 399.42,215.26 394.33,210.19 394.33,201.29 388.62,195.58 AB02.BA2
  Bottom 0.508: 297.81,266.7 288.29,266.7 287.02,265.43 A10.A2 | 297.81,266.7 299.08,265.43 A09.A2 | 310.51,266.7 311.79,265.43 A08.A2 | 310.51,266.7 297.81,266.7 | 323.21,266.7 324.49,265.43 A07.A2 | 323.21,266.7 310.51,266.7 | 323.21,266.7 386.71,266.7 387.99,265.43 AB02.AA2 | v105.41,71.12 96.52,62.23 D25.A2 | C25.A2 96.52,130.81 99.69,130.81 100.97,129.54 103.5,129.54 v105.41,127.64 108.58,130.81 v149.22,130.81 | B07.A2 325.12,194.31 325.75,193.68 329.56,193.68 330.2,193.04 332.74,193.04 334.01,194.31 337.19,194.31 B06.A2 337.82,194.31 341,194.31 342.26,193.04 344.81,193.04 347.98,196.22 | 347.98,196.22 348.62,196.85 386.71,196.85 387.99,195.58 AB02.BA2 | B16.A2 210.82,195.58 212.09,196.85 310.51,196.85 311.79,195.58 B08.A2 312.42,195.58 314.32,197.49 346.71,197.49 347.98,196.22
WRITE  (via drill 0.61)
  Top 0.381: D25.M2 96.52,30.48 97.79,31.75 97.79,50.16 96.52,51.44 93.34,51.44 D25.D2 | C25.L1 99.69,103.5 100.97,104.78 100.97,120.02 99.69,121.28 C25.D1 | v316.87,133.35 316.87,148.59 318.13,149.86 B08.S1
  Bottom 0.381: v316.87,133.35 306.7,123.19 100.33,123.19 99.69,122.56 C25.D1 | D25.D2 92.71,52.7 92.71,57.15 91.44,57.15 91.44,94.61 100.33,94.61 104.14,98.42 104.14,102.23 99.69,102.23 C25.L1
X_RETURN  (via drill 0.61)
  Top 0.381: v92.71,48.9 92.71,46.35 D25.F2
  Bottom 0.381: D25.F2 93.34,45.09 93.34,40.64 95.25,40.64 99.06,36.83 102.23,36.83 D25.K1 | v92.71,48.9 85.09,48.9 85.09,173.99 91.44,180.34 92.71,180.34 92.71,184.78 B25.D2
X_SOURCE  (via drill 0.61)
  Top 0.381: v119.38,121.92 119.38,262.89 104.14,262.89 97.79,256.54 97.79,255.91 93.34,255.91 A25.D2
  Bottom 0.381: C25.F2 93.34,114.94 93.34,110.49 95.25,110.49 99.06,106.68 102.23,106.68 C25.K1 102.87,106.68 104.14,106.68 v119.38,121.92
Y_RETURN
  Top 0.381: 100.97,22.86 96.52,22.86 D25.P2 | 100.97,22.86 100.97,19.05 102.23,17.78 D25.S1 | 100.97,22.86 100.97,24.77 118.11,41.91 118.11,253.37 111.12,253.37 110.49,254 110.49,254.63 106.05,254.63 A24.D2
Y_SOURCE  (via drill 0.61)
  Top 0.381: v107.31,92.08 107.31,180.34 106.68,180.97 106.68,184.15 106.05,184.78 B24.D2
  Bottom 0.381: C25.P2 96.52,92.71 96.52,88.27 101.6,88.27 102.23,87.63 C25.S1 102.87,87.63 v107.31,92.08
